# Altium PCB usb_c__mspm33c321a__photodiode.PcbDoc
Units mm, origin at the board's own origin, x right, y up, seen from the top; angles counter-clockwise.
Board outline 40.5 x 25 mm, 2 copper layers (Top, Bottom), stack 0 mm thick; 34 components, 22 nets, 167 pads, 56 vias.
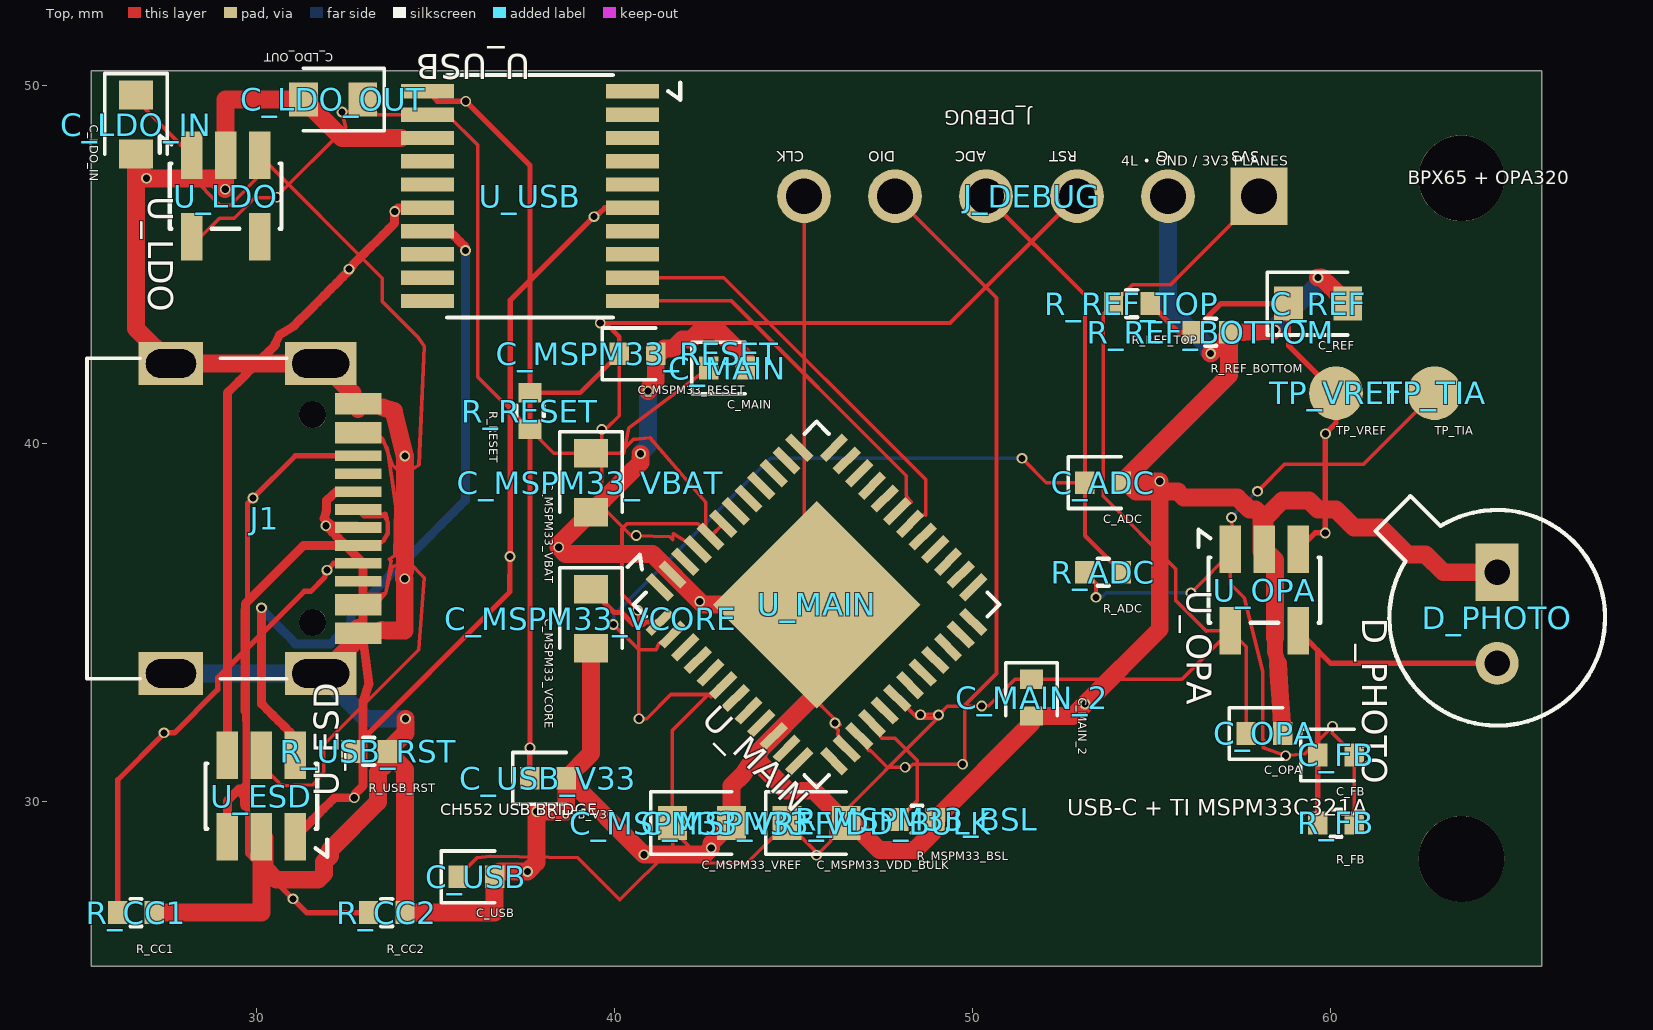
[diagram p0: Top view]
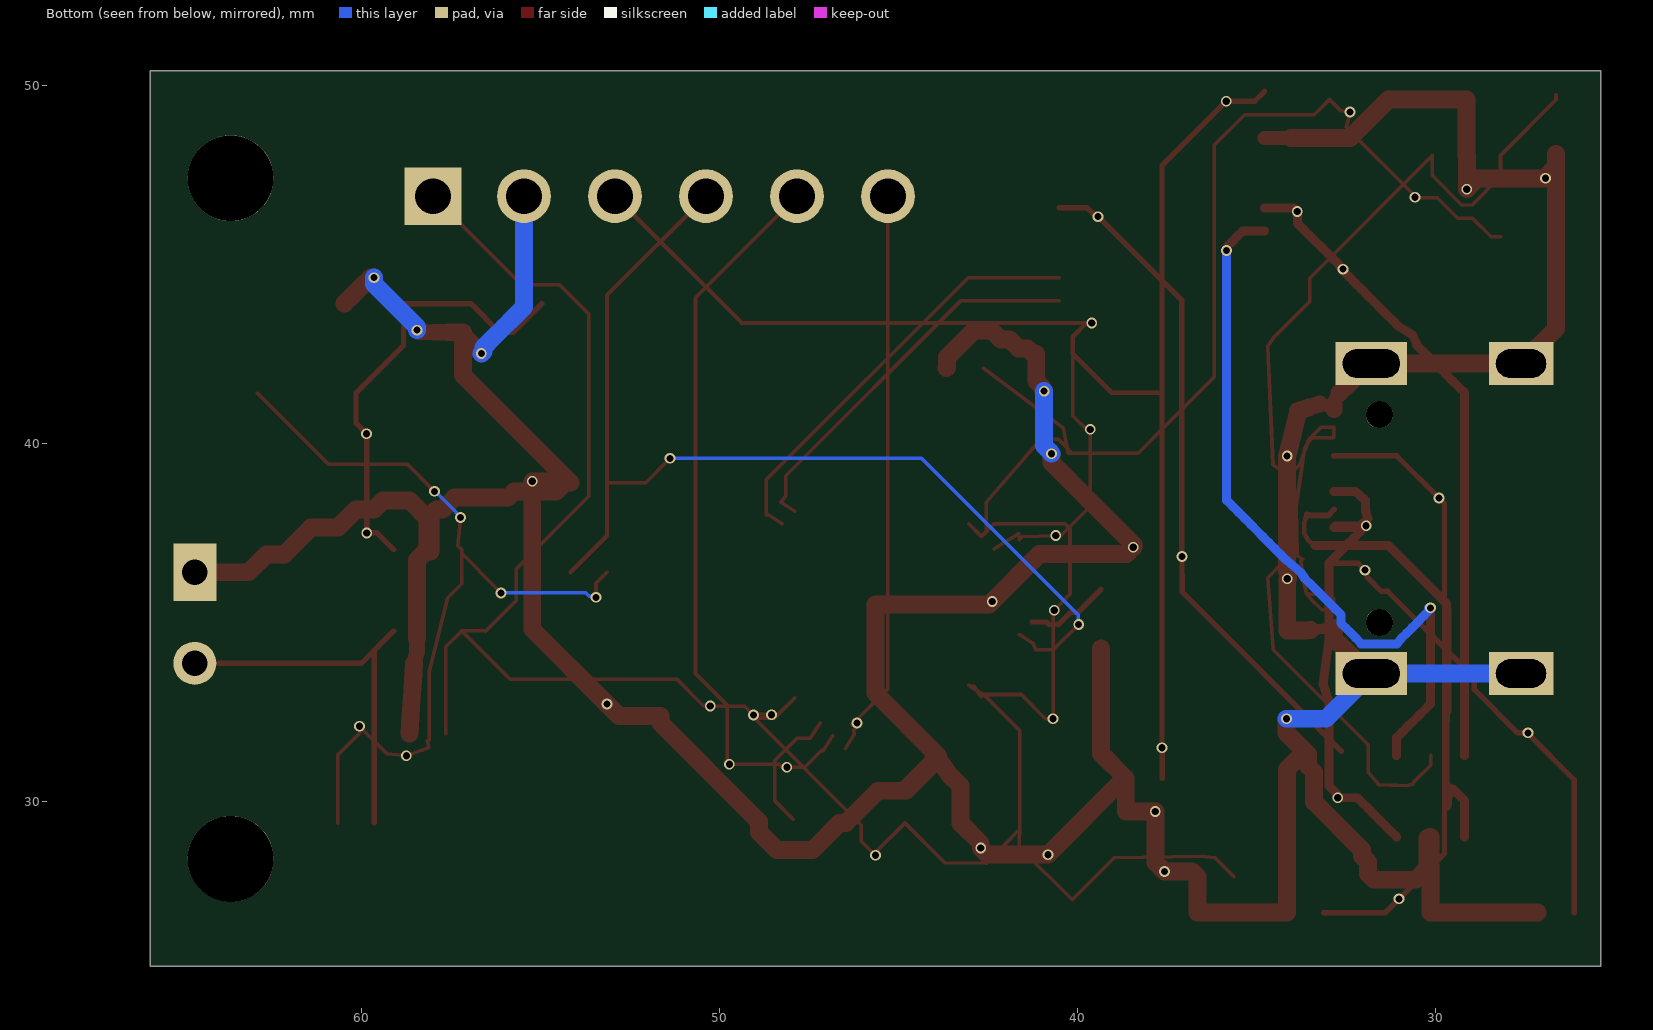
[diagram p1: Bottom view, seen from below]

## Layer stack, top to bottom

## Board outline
25.4,50.4 65.9,50.4 65.9,25.4 25.4,25.4

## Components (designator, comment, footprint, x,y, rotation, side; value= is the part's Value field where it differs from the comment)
C_ADC "" TSCIRCUIT-1.5600x0.6400mm 53.65,38.9 r0 top
C_FB "" TSCIRCUIT-1.5600x0.6400mm 60.15,31.3 r0 top
C_LDO_IN "" TSCIRCUIT-0.9500x2.4500mm 26.65,48.9 r270 top
C_LDO_OUT "" TSCIRCUIT-2.4500x0.9500mm 32.15,49.6 r180 top
C_MAIN "" TSCIRCUIT-1.5600x0.6400mm 43.15,42.1 r0 top
C_MAIN_2 "" TSCIRCUIT-0.6400x1.5600mm 51.65,32.9 r270 top
C_MSPM33_RESET "" TSCIRCUIT-1.5600x0.6400mm 40.65,42.5 r0 top
C_MSPM33_VBAT "" TSCIRCUIT-0.9500x2.4500mm 39.35,38.9 r270 top
C_MSPM33_VCORE "" TSCIRCUIT-0.9500x2.4500mm 39.35,35.1 r270 top
C_MSPM33_VDD_BULK "" TSCIRCUIT-2.4500x0.9500mm 45.65,29.4 r0 top
C_MSPM33_VREF "" TSCIRCUIT-2.4500x0.9500mm 42.45,29.4 r0 top
C_OPA "" TSCIRCUIT-1.5600x0.6400mm 58.15,31.9 r0 top
C_REF "" TSCIRCUIT-2.4500x0.9500mm 59.65,43.9 r0 top
C_USB "" TSCIRCUIT-1.5600x0.6400mm 36.15,27.9 r0 top
C_USB_V33 "" TSCIRCUIT-1.5600x0.6400mm 38.15,30.65 r0 top
D_PHOTO "" TSCIRCUIT-1.2000x3.9400mm 64.65,35.23 r270 top
J1 "" TSCIRCUIT-6.7732x9.8502mm 30.113,37.9 r90 top
J_DEBUG "" TSCIRCUIT-14.2000x1.5000mm 51.65,46.9 r180 top
R_ADC "" TSCIRCUIT-1.5600x0.6400mm 53.65,36.4 r0 top
R_CC1 "" TSCIRCUIT-1.5600x0.6400mm 26.65,26.9 r0 top
R_CC2 "" TSCIRCUIT-1.5600x0.6400mm 33.65,26.9 r0 top
R_FB "" TSCIRCUIT-1.5600x0.6400mm 60.15,29.4 r0 top
R_MSPM33_BSL "" TSCIRCUIT-1.5600x0.6400mm 48.45,29.5 r0 top
R_REF_BOTTOM "" TSCIRCUIT-1.5600x0.6400mm 56.65,43.1 r0 top
R_REF_TOP "" TSCIRCUIT-1.5600x0.6400mm 54.45,43.9 r0 top
R_RESET "" TSCIRCUIT-0.6400x1.5600mm 37.65,40.9 r270 top
R_USB_RST "" TSCIRCUIT-1.5600x0.6400mm 33.15,31.4 r0 top
TP_TIA "" TSCIRCUIT-1.5000x1.5000mm 62.9,41.4 r0 top
TP_VREF "" TSCIRCUIT-1.5000x1.5000mm 60.15,41.4 r0 top
U_ESD "" TSCIRCUIT-2.5000x3.6000mm#1 30.15,30.15 r90 top
U_LDO "" TSCIRCUIT-2.5000x3.6000mm#2 29.15,46.9 r270 top
U_MAIN "" TSCIRCUIT-9.5459x9.5459mm 45.65,35.5 r315 top
U_OPA "" TSCIRCUIT-2.5000x3.6000mm#2 58.15,35.9 r270 top
U_USB "" TSCIRCUIT-7.2000x6.2500mm 37.65,46.9 r180 top

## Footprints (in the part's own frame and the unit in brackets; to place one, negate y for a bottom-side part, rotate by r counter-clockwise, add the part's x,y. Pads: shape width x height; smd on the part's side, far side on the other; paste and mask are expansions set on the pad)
TSCIRCUIT-0.6400x1.5600mm [mm]
  rect 0.54x0.64 smd: 1(-0.51,0) 2(0.51,0)
  silkscreen extent -0.98,-0.72 0.51,0.72
TSCIRCUIT-0.9500x2.4500mm [mm]
  rect 0.8x0.95 smd: 1(-0.825,0) 2(0.825,0)
  silkscreen extent -1.42,-0.87 0.83,0.87
TSCIRCUIT-1.2000x3.9400mm [mm]
  rect 1.6x1.2 hole 0.7: 1(-1.17,0)
  round 1.2 hole 0.7: 2(1.37,0)
  silkscreen extent -3.3,-3.4 3.11,3.01
TSCIRCUIT-1.5000x1.5000mm [mm]
  round 1.5 smd: 1(0,0)
TSCIRCUIT-1.5600x0.6400mm [mm]
  rect 0.54x0.64 smd: 1(-0.51,0) 2(0.51,0)
  silkscreen extent -0.98,-0.72 0.51,0.72
TSCIRCUIT-2.4500x0.9500mm [mm]
  rect 0.8x0.95 smd: 1(-0.825,0) 2(0.825,0)
  silkscreen extent -1.43,-0.87 0.82,0.87
TSCIRCUIT-2.5000x3.6000mm#1 [mm]
  rect 1.325x0.6 smd: 1(-1.138,-0.95) 2(-1.138,0) 3(-1.138,0.95) 4(1.137,0.95) 5(1.137,0) 6(1.137,-0.95)
  silkscreen extent -1.69,-1.84 0.91,1.56
TSCIRCUIT-2.5000x3.6000mm#2 [mm]
  rect 1.325x0.6 smd: 1(-1.138,-0.95) 2(-1.138,0) 3(-1.138,0.95) 4(1.138,0.95) 5(1.138,-0.95)
  silkscreen extent -1.69,-1.84 0.91,1.56
TSCIRCUIT-6.7732x9.8502mm [mm]
  rect 0.3x1.3 smd: 1(-3.35,-2.737) 2(-3.05,-2.737) 3(-2.55,-2.737) 4(-2.25,-2.737) 5(-1.75,-2.737) 6(-1.25,-2.737) 7(-0.75,-2.737) 8(-0.25,-2.737) 9(0.25,-2.737) 10(0.75,-2.737) 11(1.25,-2.737) 12(1.75,-2.737) 13(2.55,-2.737) 14(2.25,-2.737) 15(3.35,-2.737) 16(3.05,-2.737)
  rect 1.2x2 hole 0.8 slot 1.6 at 90 deg: 17(-4.325,-1.693) 18(4.325,-1.693)
  rect 1.2x1.8 hole 0.8 slot 1.4 at 90 deg: 19(4.325,2.487) 20(-4.325,2.487)
  round 0.75 hole 0.75 unplated: NPTH-1(-2.9,-1.468) NPTH-2(2.9,-1.468)
  silkscreen extent -4.47,-0.75 4.47,4.83
TSCIRCUIT-7.2000x6.2500mm [mm]
  rect 1.475x0.4 smd: 1(-2.862,-2.925) 2(-2.862,-2.275) 3(-2.862,-1.625) 4(-2.862,-0.975) 5(-2.862,-0.325) 6(-2.862,0.325) 7(-2.862,0.975) 8(-2.862,1.625) 9(-2.862,2.275) 10(-2.862,2.925) 11(2.863,2.925) 12(2.863,2.275) 13(2.863,1.625) 14(2.863,0.975) 15(2.863,0.325) 16(2.863,-0.325) 17(2.863,-0.975) 18(2.863,-1.625) 19(2.863,-2.275) 20(2.863,-2.925)
  silkscreen extent -4.19,-3.38 2.31,3.38
TSCIRCUIT-9.5459x9.5459mm [mm]
  rect 0.875x0.25 smd: 1(-3.438,-2.75) 2(-3.438,-2.25) 3(-3.438,-1.75) 4(-3.438,-1.25) 5(-3.438,-0.75) 6(-3.438,-0.25) 7(-3.438,0.25) 8(-3.438,0.75) 9(-3.438,1.25) 10(-3.438,1.75) 11(-3.438,2.25) 12(-3.438,2.75) 25(3.438,2.75) 26(3.438,2.25) 27(3.438,1.75) 28(3.438,1.25) 29(3.438,0.75) 30(3.438,0.25) 31(3.438,-0.25) 32(3.438,-0.75) 33(3.438,-1.25) 34(3.438,-1.75) 35(3.438,-2.25) 36(3.438,-2.75)
  rect 0.25x0.875 smd: 13(-2.75,3.438) 14(-2.25,3.438) 15(-1.75,3.438) 16(-1.25,3.438) 17(-0.75,3.438) 18(-0.25,3.438) 19(0.25,3.438) 20(0.75,3.438) 21(1.25,3.438) 22(1.75,3.438) 23(2.25,3.438) 24(2.75,3.438) 37(2.75,-3.438) 38(2.25,-3.438) 39(1.75,-3.438) 40(1.25,-3.438) 41(0.75,-3.438) 42(0.25,-3.438) 43(-0.25,-3.438) 44(-0.75,-3.438) 45(-1.25,-3.438) 46(-1.75,-3.438) 47(-2.25,-3.438) 48(-2.75,-3.438)
  rect 4.1x4.1 smd: 49(0,0)
  silkscreen extent -4.47,-3.61 3.61,3.61
TSCIRCUIT-14.2000x1.5000mm [mm]
  rect 1.6x1.6 hole 1: 1(-6.35,0)
  round 1.5 hole 1: 2(-3.81,0) 3(-1.27,0) 4(1.27,0) 5(3.81,0) 6(6.35,0)

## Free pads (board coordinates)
  round 2.4 hole 2.4 unplated: NPTH-3(63.65,47.4) NPTH-4(63.65,28.4)

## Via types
v1: diameter 0.3, hole 0.2, Top to Bottom, 56 vias

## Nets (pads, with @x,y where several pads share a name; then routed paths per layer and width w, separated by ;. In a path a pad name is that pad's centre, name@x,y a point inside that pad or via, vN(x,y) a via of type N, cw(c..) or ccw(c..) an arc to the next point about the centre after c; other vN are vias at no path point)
".U_USB > .pin9 to .U_MAIN > .pin19": U_MAIN.19 U_USB.9 | length 12
  Top w0.1: U_USB.9 43.062,44.625 48.695,38.991 48.695,37.995 48.645,38.009 U_MAIN.19
".U_USB > .pin10 to .U_MAIN > .pin18": U_MAIN.18 U_USB.10 | length 10.9
  Top w0.1: U_USB.10 43.272,43.975 48.149,39.098 48.149,38.543 48.29,38.361 U_MAIN.18
ADC_IN: C_ADC.1 J_DEBUG.4 R_ADC.2 U_MAIN.47 | length 29.7
  Top w0.1: v1(39.975,34.945) 40.695,34.233 41.176,34.233 41.243,34.406 U_MAIN.47 ; v1(51.384,39.581) 51.411,39.554 52.065,38.9 C_ADC.1
  Top w0.12: J_DEBUG.4 53.14,44.14 C_ADC.1 53.14,37.42 R_ADC.2
  Bottom w0.1: v1(39.975,34.945) 39.942,34.986 39.99,35.034 39.99,35.207 44.364,39.581 v1(51.384,39.581)
GND: C_ADC.2 C_LDO_IN.2 C_LDO_OUT.2 C_MAIN.2 C_MAIN_2.2 C_MSPM33_RESET.2 C_MSPM33_VBAT.2 C_MSPM33_VCORE.2 C_MSPM33_VDD_BULK.2 C_MSPM33_VREF.2 C_OPA.2 C_REF.2 C_USB.2 C_USB_V33.2 D_PHOTO.1 J1.1 J1.2 J1.15 J1.16 J1.17 J1.18 J1.19 J1.20 J_DEBUG.2 R_CC1.2 R_CC2.2 R_MSPM33_BSL.2 R_REF_BOTTOM.2 R_USB_RST.2 U_ESD.2 U_LDO.2 U_MAIN.39 U_MAIN.49 U_OPA.2 U_USB.18 | length 161.8
  Top w0.25: U_MAIN.39@44.147,31.523 U_MAIN.39 U_MAIN.39@44.147,31.523
  Top w0.3: J1.1@32.699,34.4 J1.1 J1.1@32.849,34.7 ; J1.15@32.699,41.4 J1.15 J1.16@32.849,41.1 ; J1.2 33.499,34.789 ; J1.16 J1.16@33.25,41.1
  Top w0.325: v1@58.398,43.1 58.406,43.108 58.406,43.116 v1(58.45,43.16)
  Top w0.4: U_USB.18@34.05,48.525 U_USB.18
  Top w0.425: 57.985,43.1 v1@58.398,43.1
  Top w0.437: 58.445,34.569 58.447,34.181 58.527,33.85
  Top w0.45: 57.573,43.1 57.985,43.1
  Top w0.475: J1.16 J1.16@32.849,41.1 ; J1.16@33.25,41.1 33.55,41
  Top w0.5: R_CC1.2 30.15,26.9 U_ESD.2 30.179,28.983 30.233,28.983 30.233,28.15 30.567,27.817 31.733,27.817 31.9,27.983 31.9,28.317 32.067,28.483 32.067,28.65 33.4,29.983 33.4,30.817 33.567,30.983 33.567,31.317 33.65,31.4 R_USB_RST.2 ; J1.17 31.874,33.575 32.474,34.175 J1.1@32.699,34.4 ; J1.15@32.699,41.4 32.474,41.625 31.874,42.225 J1.18 J1.19 26.65,43.201 C_LDO_IN.2 26.65,47.727 26.934,47.443 26.934,47.408 v1(26.944,47.398) 28.835,47.398 v1(29.139,47.094) 29.139,48.027 U_LDO.2 29.15,49.6 C_LDO_OUT.2 32.4,48.525 34.05,48.525 ; J1.1@32.849,34.7 J1.2 ; 33.499,34.789 33.65,34.775 34.152,34.775 v1(34.152,36.217) 34.137,36.232 34.137,36.405 34.155,36.423 34.155,36.883 34.155,37.344 34.155,37.804 34.155,38.265 34.155,38.725 34.155,39.186 v1(34.155,39.646) 33.85,40.9 33.55,41 ; v1(34.172,32.312) 34.172,31.912 R_USB_RST.2 ; C_MSPM33_VCORE.2 39.35,31.34 C_USB_V33.2 ; v1(40.733,39.71) 40.733,39.458 40.387,39.112 40.041,38.767 39.696,38.421 C_MSPM33_VBAT.2 38.45,37.175 v1(38.45,37.1) 38.644,36.906 41.041,36.906 41.068,36.906 v1(42.388,35.586) 42.474,35.5 U_MAIN.49 45.65,33.025 43.9,31.275 43.9,31.195 44.287,30.808 44.795,30.3 45.45,30.3 45.575,30.3 ; v1(40.939,41.457) 40.991,41.509 40.991,41.57 41.16,41.739 41.16,42.119 C_MSPM33_RESET.2 41.25,42.5 41.4,42.65 41.65,42.65 41.9,42.9 42.15,42.9 42.4,43.15 42.9,43.15 43.65,42.4 43.65,42.11 C_MAIN.2 ; v1(56.65,42.508) 57.16,43.018 R_REF_BOTTOM.2 ; 57.573,43.1 R_REF_BOTTOM.2 ; 58.445,34.569 58.445,36.743 U_OPA.2 ; 58.527,33.85 58.56,33.363 58.593,32.875 58.627,32.387 C_OPA.2 ; v1(59.65,44.625) 59.75,44.625 59.992,44.383 60.233,44.142 C_REF.2 ; D_PHOTO.1 63.15,36.4 62.65,36.9 62.15,36.9 61.4,37.65 60.65,37.65 60.15,38.15 59.65,38.15 59.4,38.4 58.65,38.4 58.15,37.9 U_OPA.2 ; R_USB_RST.2 34.16,30.9 R_CC2.2 36.66,26.9 C_USB.2 36.81,28.05 37.196,28.05 v1(37.582,28.05) 37.603,28.071 37.835,28.303 37.835,28.776 37.835,29.25 v1(37.835,29.723) 38.66,29.723 C_USB_V33.2 ; C_USB_V33.2 38.7,30.65 v1(40.834,28.516) 42.523,28.516 v1(42.709,28.702) 42.709,28.834 C_MSPM33_VREF.2 43.275,29.747 43.275,30.093 43.275,30.44 43.592,30.757 44.025,31.4 44.025,31.125 44.85,30.3 45.575,30.3 ; 45.575,30.3 C_MSPM33_VDD_BULK.2 ; 45.575,30.3 C_MSPM33_VDD_BULK.2 ; C_MSPM33_VDD_BULK.2 46.65,29.4 47.4,28.65 48.4,28.65 48.9,29.15 48.9,29.44 R_MSPM33_BSL.2 51.65,32.19 C_MAIN_2.2 52.811,32.39 v1(53.144,32.723) 55.23,34.809 55.23,38.858 v1(55.23,38.94) 54.2,38.94 C_ADC.2 ; C_ADC.2 54.317,38.9 54.567,38.65 55.733,38.65 55.9,38.483 57.4,38.483 57.733,38.15 57.9,38.15 58.067,37.983 58.067,36.983 58.096,36.983 U_OPA.2 ; C_ADC.2 57.16,41.9 R_REF_BOTTOM.2 ; 44.025,31.4 44.147,31.523 44.025,31.4
  Bottom w0.5: J1.20 J1.17 33.068,32.312 v1(34.172,32.312) ; v1(40.733,39.71) 40.781,39.758 40.781,39.773 40.939,39.931 40.939,40.313 40.939,40.694 40.939,41.076 v1(40.939,41.457) ; J_DEBUG.2 55.46,46.458 55.46,46.017 55.46,45.575 55.46,45.133 55.46,44.691 55.46,44.25 55.46,43.808 55.742,43.525 56.025,43.243 56.307,42.96 56.59,42.678 56.59,42.568 v1(56.65,42.508) ; v1(58.45,43.16) 58.45,43.252 58.75,43.552 59.05,43.852 59.35,44.152 59.65,44.452 v1(59.65,44.625)
MAIN_RESET: C_MSPM33_RESET.1 J_DEBUG.3 R_RESET.1 U_MAIN.4 | length 26.8
  Top w0.1: C_MSPM33_RESET.1 40.14,40.771 39.772,40.403 39.739,40.403 v1(39.653,40.39) 39.653,38.24 40.558,37.335 v1(40.615,37.425) 41.55,37.392 41.634,37.308 41.654,37.475 U_MAIN.4
  Top w0.12: R_RESET.1 39.05,41.41 C_MSPM33_RESET.1 40.14,42.974 39.768,43.346 39.623,43.346 v1(39.612,43.357) 49.377,43.357 J_DEBUG.3
MSPM33_BSL_INVOKE: R_MSPM33_BSL.1 U_MAIN.33 | length 3.6
  Top w0.1: U_MAIN.33 47.473,31.762 47.599,31.761 47.849,31.761 48.454,31.155 48.454,31.037 48.454,30.014 R_MSPM33_BSL.1
MSPM33_SWCLK: J_DEBUG.6 U_MAIN.35 | length 16.2
  Top w0.1: J_DEBUG.6 45.3,33.156 46.31,32.145 46.208,32.145 v1(46.16,32.193) 46.16,32.086 46.26,31.986 46.243,31.871 U_MAIN.35
MSPM33_SWDIO: J_DEBUG.5 U_MAIN.34 | length 20.8
  Top w0.1: U_MAIN.34 47.118,31.412 47.144,31.434 47.619,30.959 v1(48.121,30.959) 48.132,30.97 48.259,30.97 48.331,31.042 v1(49.727,31.042) 49.78,31.095 49.78,31.195 49.78,32.681 50.672,33.573 50.672,44.068 J_DEBUG.5
MSPM33_VCORE: C_MSPM33_VCORE.1 U_MAIN.48 | length 2.4
  Top w0.15: C_MSPM33_VCORE.1 39.999,35.284 40.2,35.276 40.533,34.943 40.804,34.943 40.875,35.014 U_MAIN.48
PD_SUM: C_FB.1 D_PHOTO.2 R_FB.1 U_OPA.4 | length 11.5
  Top w0.15: R_FB.1 C_FB.1 59.64,34.222 U_OPA.4 60.002,33.86 D_PHOTO.2
TIA_OUT: C_FB.2 R_ADC.1 R_FB.2 TP_TIA.1 U_OPA.1 | length 24.3
  Top w0.1: R_ADC.1 53.45,36.09 v1(53.45,35.7) ; v1(56.099,35.825) 56.217,35.943 56.217,35.945 57.2,36.928 U_OPA.1 ; v1(57.231,37.928) 57.306,37.143 U_OPA.1 ; v1(57.956,38.659) 58.011,38.714 58.013,38.714 58.72,39.421 60.921,39.421 TP_TIA.1 ; R_FB.2 C_FB.2 60.05,31.91 v1(60.05,32.1) 59.974,32.024 59.974,32.018 59.286,31.33 v1(58.744,31.276) 58.119,31.503 58.162,31.686 58.109,31.733 58.108,33.641 57.588,35.69 57.2,36.082 U_OPA.1
  Bottom w0.1: v1(53.45,35.7) 53.477,35.727 53.641,35.727 53.739,35.825 v1(56.099,35.825) ; v1(57.231,37.928) 57.352,38.049 57.352,38.076 57.864,38.588 v1(57.956,38.659)
USB_BRIDGE_RESET: R_USB_RST.1 U_USB.6 | length 18.9
  Top w0.15: R_USB_RST.1 37.084,35.854 v1(37.089,36.842) 37.096,36.849 37.096,43.991 v1(39.433,46.328) 39.521,46.416 39.579,46.416 39.738,46.575 U_USB.6
USB_BRIDGE_V33: C_USB_V33.1 U_USB.20 | length 20.8
  Top w0.15: U_USB.20 35.063,49.55 v1(35.854,49.55) 35.901,49.503 37.65,47.754 v1(37.65,31.5) 37.646,31.496 37.646,31.398 37.64,31.392 C_USB_V33.1
USB_CC1: J1.6 R_CC1.1 | length 13.2
  Top w0.15: R_CC1.1 26.14,30.607 27.408,31.875 27.408,31.896 v1(27.43,31.918) 27.723,31.918 28.929,33.124 28.929,33.453 31.347,35.871 31.531,35.871 31.927,36.268 31.927,36.407 v1(31.98,36.46) 32.17,36.65 J1.6
USB_CC2: J1.12 R_CC2.1 | length 17.5
  Top w0.15: J1.12 31.096,39.65 v1(29.917,38.471) 29.895,38.449 29.762,38.316 29.762,38.256 29.762,28.553 v1(31.032,27.283) 31.044,27.271 31.415,26.9 R_CC2.1
USB_DM_MCU: U_ESD.4 U_USB.15 | length 18.1
  Top w0.25: U_ESD.4 29.2,31.534 29.2,31.781 29.2,32.028 29.2,32.275 29.2,32.522 29.2,32.768 29.2,33.015 29.2,33.262 29.2,33.509 29.2,33.756 29.2,34.003 29.2,34.249 29.2,34.496 29.2,34.743 29.2,34.99 29.2,35.237 29.2,35.484 29.2,35.73 29.2,35.977 29.2,36.224 29.2,36.471 29.2,36.718 29.2,36.965 29.2,37.211 29.2,37.458 29.2,37.705 29.2,37.952 29.2,38.199 29.2,38.446 29.2,38.692 29.2,38.939 29.2,39.186 29.2,39.433 29.2,39.68 29.2,39.927 29.2,40.173 29.2,40.42 29.2,40.667 29.2,40.914 29.2,41.161 29.2,41.408 29.365,41.572 29.53,41.737 29.694,41.902 29.859,42.067 30.024,42.232 30.189,42.396 30.354,42.561 30.519,42.726 30.551,42.759 30.525,42.775 30.65,43.025 31.036,43.256 31.21,43.43 31.383,43.603 31.557,43.777 31.73,43.95 31.904,44.124 32.077,44.297 32.251,44.471 32.424,44.645 32.598,44.818 v1(32.598,44.862) 32.688,44.952 32.688,44.965 32.857,45.134 33.026,45.303 33.195,45.472 33.364,45.641 33.533,45.81 33.702,45.979 33.871,46.148 33.871,46.311 v1(33.871,46.474) 33.969,46.572 34.039,46.572 34.042,46.575 34.29,46.575 34.539,46.575 U_USB.15
USB_DM_PORT: J1.7 J1.9 U_ESD.3 | length 13.8
  Top w0.125: 29.681,30.409 29.681,30.642 29.682,30.874 29.683,31.107 29.683,31.34 29.684,31.573 29.685,31.806 29.685,32.038 29.686,32.271 ; J1.7@33.375,37.15 33.561,37.278 33.675,37.475 33.679,37.624 33.683,37.773 33.642,37.892
  Top w0.138: 33.601,38.011 33.642,37.892
  Top w0.162: 29.686,32.271 29.687,32.521 ; J1.9 33.018,37.981 33.245,37.981 33.473,37.981 33.601,38.011
  Top w0.25: U_ESD.3 29.2,29.214 29.2,29.416 29.2,29.618 29.2,29.819 29.2,30.021 29.365,30.188 29.53,30.355 29.69,30.09 29.687,29.874 29.68,29.943 29.68,30.176 29.681,30.409 ; 29.687,32.521 29.688,32.771 29.689,33.021 29.69,33.271 29.691,33.521 29.692,33.771 29.693,34.021 29.695,34.271 29.696,34.521 29.697,34.771 29.698,35.021 29.699,35.271 29.7,35.521 29.863,35.684 30.026,35.847 30.189,36.01 30.352,36.172 30.515,36.335 30.677,36.498 30.84,36.661 31.003,36.824 31.166,36.987 31.329,37.15 31.546,37.15 31.763,37.15 31.981,37.15 32.198,37.15 32.415,37.15 32.632,37.15 J1.7 33.024,37.15 33.2,37.15 J1.7@33.375,37.15
USB_DP_MCU: U_ESD.6 U_USB.14 | length 20.8
  Top w0.25: v1(30.155,35.407) 30.155,35.163 30.155,34.92 30.155,34.676 30.155,34.432 30.155,34.189 30.155,33.945 30.155,33.702 30.155,33.458 30.155,33.214 30.155,32.971 30.155,32.727 30.313,32.569 30.47,32.412 30.628,32.254 30.785,32.097 30.943,31.939 31.101,31.781 31.101,31.535 U_ESD.6 ; U_USB.14 34.991,45.925 35.194,45.925 35.397,45.925 35.543,45.778 35.69,45.632 35.836,45.485 35.836,45.395 v1(35.849,45.382)
  Bottom w0.25: v1(30.155,35.407) 30.212,35.407 30.212,35.312 30.364,35.16 30.516,35.008 30.668,34.856 30.82,34.704 30.972,34.552 31.087,34.4 32.087,34.4 32.243,34.571 32.379,34.708 32.516,34.845 32.653,34.981 32.647,35.213 32.815,35.381 32.984,35.549 33.152,35.717 33.32,35.885 33.489,36.053 33.657,36.222 33.775,36.4 34.162,36.726 34.33,36.894 34.499,37.062 34.667,37.23 34.835,37.398 35.004,37.567 35.172,37.735 35.34,37.903 35.509,38.071 35.677,38.239 35.845,38.407 35.845,38.656 35.846,38.905 35.846,39.154 35.846,39.404 35.846,39.653 35.846,39.902 35.846,40.151 35.846,40.4 35.846,40.649 35.847,40.898 35.847,41.147 35.847,41.396 35.847,41.645 35.847,41.895 35.847,42.144 35.847,42.393 35.848,42.642 35.848,42.891 35.848,43.14 35.848,43.389 35.848,43.638 35.848,43.887 35.848,44.136 35.848,44.386 35.849,44.635 35.849,44.884 35.849,45.133 v1(35.849,45.382)
USB_DP_PORT: J1.8 J1.10 U_ESD.1 | length 13.7
  Top w0.25: U_ESD.1 31.256,29.169 31.413,29.325 31.569,29.481 31.725,29.637 31.881,29.794 32.038,29.95 32.194,30.106 32.377,30.106 32.56,30.106 v1(32.743,30.106) 32.774,30.137 32.774,30.224 32.883,30.333 32.992,30.442 32.992,30.633 32.992,30.874 32.992,31.115 32.992,31.356 32.992,31.597 32.992,31.838 32.992,32.079 32.992,32.32 32.992,32.561 32.992,32.802 33.15,33.275 32.992,34.489 32.992,34.73 32.992,34.971 32.992,35.212 32.992,35.453 32.992,35.694 32.992,35.935 32.992,36.176 32.992,36.417 32.992,36.658 32.818,36.832 32.645,37.005 32.471,37.179 32.297,37.353 32.124,37.526 v1(31.95,37.7) 31.982,37.668 32.107,37.668 32.124,37.65 32.366,37.65 32.607,37.65 J1.8 32.811,37.688 32.595,37.688 32.379,37.688 32.162,37.688 32.152,37.671 31.9,37.9 31.968,38.127 31.968,38.364 31.962,38.4 32.253,38.65 32.452,38.65 32.651,38.65 J1.10
VBUS5: C_LDO_IN.1 J1.3 J1.4 J1.13 J1.14 U_ESD.5 U_LDO.1 U_LDO.3 | length 37.5
  Top w0.1: C_LDO_IN.1 26.65,49.588 U_LDO.1 ; U_LDO.1 28.199,47.454 28.99,46.655 29.284,46.648 30.103,47.486 U_LDO.3 33.526,44.611 33.526,43.959 34.523,42.962 34.7,42.7 34.55,39.4 34.1,39.1 33.8,39.4 33.553,40.105 33.208,40.45 J1.13 ; U_ESD.5 30.15,31.015 30.63,30.535 30.654,30.489 30.845,30.446 31.05,30.46 31.251,30.453 31.592,30.469 31.891,30.811 31.891,31.584 34.544,34.237 34.7,36.25 34.25,36.7 33.8,36.55 33.626,35.822 33.481,35.641 33.19,35.35 J1.3 J1.4 32.99,35.791 33.527,35.791 33.626,35.824 33.769,36.724 33.725,36.768 33.879,36.867 33.908,38.239 33.661,39.879 33.508,40.105 33.463,40.15 J1.14 J1.13
VCC_3V3: C_LDO_OUT.1 C_MAIN.1 C_MAIN_2.1 C_MSPM33_VBAT.1 C_MSPM33_VDD_BULK.1 C_MSPM33_VREF.1 C_OPA.1 C_USB.1 J_DEBUG.1 R_REF_TOP.1 R_RESET.2 U_LDO.5 U_MAIN.5 U_MAIN.6 U_MAIN.31 U_MAIN.43 U_OPA.5 U_USB.19 | length 96.8
  Top w0.1: U_LDO.5 28.459,45.762 28.983,46.287 29.396,46.287 29.659,46.55 29.969,46.86 30.538,46.86 30.574,46.86 v1(30.583,46.869) 30.583,46.894 32.507,48.818 32.507,48.821 v1(32.4,49.25) 32.654,49.279 C_LDO_OUT.1 33.4,49.175 U_USB.19 35.342,49.175 36.187,48.33 36.187,41.853 R_RESET.2 38.315,39.725 C_MSPM33_VBAT.1 ; C_USB.1 36.17,28.43 36.545,28.47 38.981,28.43 40.155,27.256 41.635,28.727 C_MSPM33_VREF.1 ; C_MAIN.1 40.407,40.424 40.265,39.725 C_MSPM33_VBAT.1 ; U_MAIN.5 U_MAIN.6 ; C_OPA.1 57.64,34.322 U_OPA.5 ; J_DEBUG.1 55.53,44.43 54.47,44.43 R_REF_TOP.1 53.65,43.61 53.65,38.52 55.678,36.493 55.678,35.612 56.527,34.762 U_OPA.5 ; C_MSPM33_VBAT.1 40.152,39.725 40.533,40.106 41,40.15 42.555,38.349 42.555,37.534 U_MAIN.5 42.336,37.753 40.357,37.753 40.218,37.614 40.218,35.791 v1(40.658,35.34) 40.741,35.268 40.689,35.216 v1(40.689,32.31) 40.694,32.315 40.907,32.315 41.581,32.989 42.627,32.989 42.703,32.923 42.896,33.217 U_MAIN.43 42.655,32.991 42.623,32.986 41.625,31.988 C_MSPM33_VREF.1 ; C_MSPM33_VREF.1 41.623,29.223 42.547,28.274 43.713,28.288 C_MSPM33_VDD_BULK.1 45.65,28.575 v1(45.65,28.5) 45.65,28.504 46.041,28.895 46.041,29.339 49.051,32.349 v1(49.051,32.416) 48.968,32.333 48.922,32.333 48.464,32.333 U_MAIN.31 48.381,32.416 v1(48.55,32.425) 49.095,32.459 49.3,32.664 v1(50.258,32.664) 50.271,32.677 50.454,32.677 51.187,33.41 C_MAIN_2.1 55.848,33.41 U_OPA.5
VREF_0V5: C_REF.1 R_REF_BOTTOM.1 R_REF_TOP.2 TP_VREF.1 U_OPA.3 | length 12.5
  Top w0.15: R_REF_TOP.2 55.76,43.1 R_REF_BOTTOM.1 56.94,43.9 C_REF.1 58.825,42.725 TP_VREF.1 60.15,40.571 59.852,40.274 v1(59.853,40.266) 59.853,37.522 59.85,37.519 v1(59.85,37.5) 59.563,37.5 U_OPA.3
pads on no net: J1.5 J1.11 J1.NPTH-1 J1.NPTH-2 U_LDO.4 U_MAIN.1 U_MAIN.2 U_MAIN.3 U_MAIN.7 U_MAIN.8 U_MAIN.9 U_MAIN.10 U_MAIN.11 U_MAIN.12 U_MAIN.13 U_MAIN.14 U_MAIN.15 U_MAIN.16 U_MAIN.17 U_MAIN.20 U_MAIN.21 U_MAIN.22 U_MAIN.23 U_MAIN.24 U_MAIN.25 U_MAIN.26 U_MAIN.27 U_MAIN.28 U_MAIN.29 U_MAIN.30 U_MAIN.32 U_MAIN.36 U_MAIN.37 U_MAIN.38 U_MAIN.40 U_MAIN.41 U_MAIN.42 U_MAIN.44 U_MAIN.45 U_MAIN.46 U_USB.1 U_USB.2 U_USB.3 U_USB.4 U_USB.5 U_USB.7 U_USB.8 U_USB.11 U_USB.12 U_USB.13 U_USB.16 U_USB.17

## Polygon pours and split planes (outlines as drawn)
GND on Mid1 (solid): 65.6,50.1 25.7,50.1 25.7,25.7 65.6,25.7
VCC_3V3 on Mid2 (solid): 65.6,50.1 25.7,50.1 25.7,25.7 65.6,25.7

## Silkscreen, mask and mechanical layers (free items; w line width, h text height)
Top Overlay:
  text "4L • GND / 3V3 PLANES" at 54.15,47.65 h0.48
  text "BPX65 + OPA320" at 62.15,47.1 h0.65
  text "CH552 USB BRIDGE" at 35.15,29.5 h0.55
  text "USB-C + TI MSPM33C321A" at 52.65,29.45 h0.78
